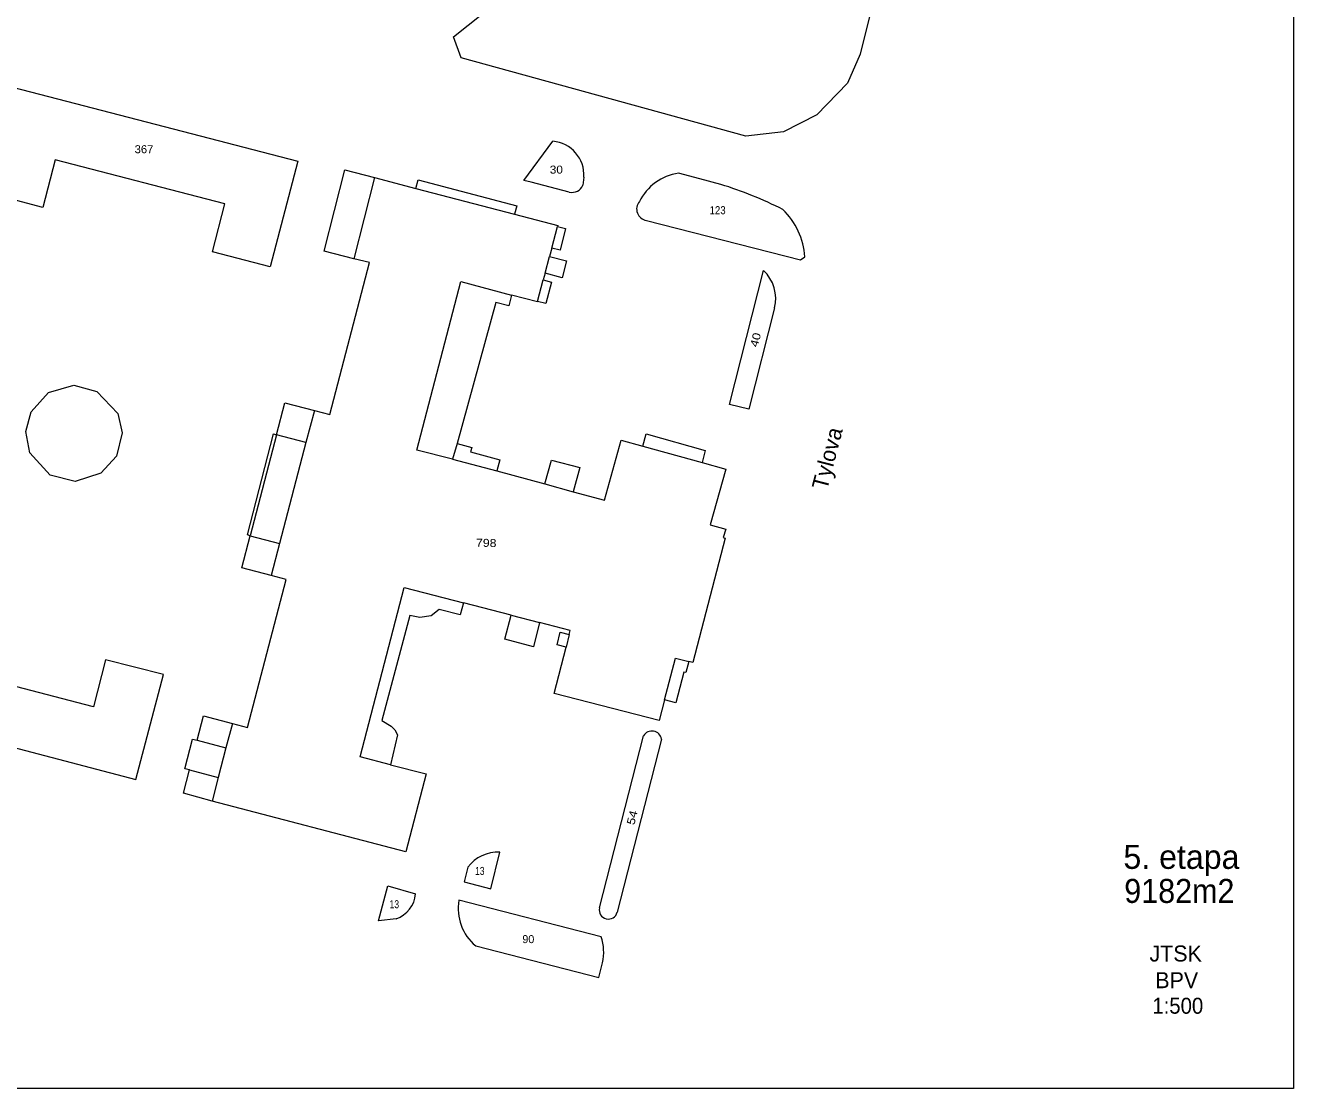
# Model space of a CAD drawing. Extents: x -843398 to -843100, y -1003450 to -1003185.
# Drawn here: x -843258.5 to -843100, y -1003450.4 to -1003317.5 of the extents above; entities that cross this region are included whole.
import ezdxf
from ezdxf.enums import TextEntityAlignment as Align

# ---------------------------------------------------------------- set-up
doc = ezdxf.new("R2010")
doc.units = 0
doc.header["$LTSCALE"] = 0.4
doc.layers.add('20', color=7, linetype='Continuous')
for name, color, linetype, lineweight in [('35', 7, 'Continuous', 13), ('36', 7, 'Continuous', 13), ('38', 7, 'Continuous', 13), ('43', 7, 'Continuous', 13), ('44', 7, 'Continuous', 13)]:
    doc.layers.add(name, color=color, linetype=linetype, lineweight=lineweight)

msp = doc.modelspace()

# ---------------------------------------------------------------- linework, layer by layer
at = {"layer": '36'}
for p, q in [((-843214.84, -1003336.5), (-843217.4, -1003346.66)), ((-843209.67, -1003337.87), (-843197.32, -1003341.09)), ((-843192.67, -1003345.33), (-843191.95, -1003342.62)), ((-843193.52, -1003348.48), (-843192.95, -1003346.37)), ((-843194.46, -1003352.01), (-843193.74, -1003349.31)), ((-843181.28, -1003370.1), (-843173.9, -1003372.15)), ((-843193.54, -1003374.82), (-843190.01, -1003375.79)), ((-843197.76, -1003391.23), (-843194.21, -1003392.15)), ((-843190.49, -1003393.65), (-843190.9, -1003395.24)), ((-843237, -1003406.86), (-843233.4, -1003407.8)), ((-843237.97, -1003410.57), (-843234.37, -1003411.51))]:
    msp.add_line(p, q, dxfattribs=at)
for points in [[(-843205.07, -1003371.72), (-843209.54, -1003370.58), (-843204.05, -1003349.5), (-843197.7, -1003351.2)], [(-843222.35, -1003365.62), (-843223.4, -1003369.63), (-843226.69, -1003382.25), (-843227.74, -1003386.26)], [(-843223.4, -1003369.63), (-843227.08, -1003368.67), (-843230.37, -1003381.29), (-843226.69, -1003382.25)], [(-843204.52, -1003369.77), (-843205.07, -1003371.72), (-843199.55, -1003373.19)], [(-843212.84, -1003409.91), (-843216.64, -1003408.92), (-843211.12, -1003387.76), (-843203.72, -1003389.68)], [(-843178.57, -1003401.8), (-843177.21, -1003396.58), (-843175.55, -1003397.01)], [(-843232.6, -1003404.75), (-843233.4, -1003407.8), (-843234.37, -1003411.51), (-843235.14, -1003414.48)]]:
    msp.add_lwpolyline(points, dxfattribs=at)
msp.add_lwpolyline([(-843255.58, -1003363.39), (-843252.41, -1003362.48), (-843249.54, -1003363.25), (-843246.92, -1003366.03), (-843246.39, -1003368.44), (-843247.1, -1003371.33), (-843249.04, -1003373.47), (-843252.23, -1003374.5), (-843255.39, -1003373.7), (-843257.9, -1003370.92), (-843258.41, -1003368.27), (-843257.77, -1003365.8)], close=True, dxfattribs=at)
at = {"layer": '38'}
msp.add_lwpolyline([(-843210.9, -1003420.8), (-843235.14, -1003414.48), (-843238.72, -1003413.46), (-843237.97, -1003410.57), (-843238.56, -1003410.41), (-843237.6, -1003406.71), (-843237, -1003406.86), (-843236.21, -1003403.82), (-843232.6, -1003404.75), (-843230.7, -1003405.25), (-843225.87, -1003386.75), (-843227.74, -1003386.26), (-843231.42, -1003385.3), (-843230.37, -1003381.29), (-843230.73, -1003381.19), (-843227.44, -1003368.57), (-843227.08, -1003368.67), (-843226.03, -1003364.66), (-843222.35, -1003365.62), (-843220.43, -1003366.12), (-843215.48, -1003347.15), (-843217.4, -1003346.66), (-843221.11, -1003345.73), (-843218.54, -1003335.56), (-843214.84, -1003336.5), (-843209.67, -1003337.87), (-843209.39, -1003336.81), (-843197.04, -1003340.03), (-843197.32, -1003341.09), (-843191.92, -1003342.5), (-843191.95, -1003342.62), (-843190.96, -1003342.88), (-843191.63, -1003345.6), (-843192.67, -1003345.33), (-843192.95, -1003346.37), (-843190.84, -1003346.93), (-843191.4, -1003349.05), (-843193.52, -1003348.48), (-843193.74, -1003349.31), (-843192.72, -1003349.58), (-843193.44, -1003352.28), (-843194.46, -1003352.01), (-843194.47, -1003352.06), (-843197.7, -1003351.2), (-843198.06, -1003352.56), (-843199.69, -1003352.13), (-843204.52, -1003369.77), (-843202.68, -1003370.27), (-843202.83, -1003370.82), (-843199.17, -1003371.81), (-843199.55, -1003373.19), (-843193.54, -1003374.82), (-843192.73, -1003371.83), (-843189.19, -1003372.78), (-843190.01, -1003375.79), (-843186.09, -1003376.86), (-843184, -1003369.34), (-843181.28, -1003370.1), (-843180.88, -1003368.57), (-843173.5, -1003370.62), (-843173.9, -1003372.15), (-843170.94, -1003372.97), (-843172.87, -1003379.92), (-843170.94, -1003380.45), (-843171.24, -1003381.52), (-843171.02, -1003381.58), (-843175.06, -1003397.14), (-843175.55, -1003397.01), (-843175.91, -1003398.4), (-843176.19, -1003398.33), (-843177.19, -1003402.16), (-843178.57, -1003401.8), (-843179.24, -1003404.37), (-843192.38, -1003401.01), (-843190.9, -1003395.24), (-843192.02, -1003394.95), (-843191.61, -1003393.36), (-843190.49, -1003393.65), (-843190.36, -1003393.15), (-843194.21, -1003392.15), (-843194.98, -1003395.16), (-843198.54, -1003394.24), (-843197.76, -1003391.23), (-843203.72, -1003389.68), (-843204.11, -1003391.2), (-843206.76, -1003390.52), (-843207.74, -1003391.3), (-843209.19, -1003391.53), (-843210.41, -1003391.25), (-843213.9, -1003404.4), (-843212.75, -1003405.09), (-843212.31, -1003405.54), (-843211.95, -1003406.2), (-843212.84, -1003409.91), (-843208.36, -1003411.07)], close=True, dxfattribs=at)
at = {"layer": '43'}
for p, q in [((-843196.167, -1003336.865), (-843192.547, -1003331.975)), ((-843188.662, -1003336.457), (-843188.79, -1003337.472)), ((-843170.474, -1003364.866), (-843166.22, -1003348.14)), ((-843186.719, -1003427.811), (-843181.2, -1003406.299)), ((-843178.973, -1003406.708), (-843184.5, -1003428.34)), ((-843200.306, -1003425.42), (-843199.173, -1003420.858)), ((-843213.185, -1003425.059), (-843209.697, -1003426.049)), ((-843186.486, -1003431.422), (-843204.283, -1003426.86))]:
    msp.add_line(p, q, dxfattribs=at)
for points in [[(-843204.95, -1003318.93), (-843183.6, -1003301.89), (-843179.12, -1003299.8), (-843172.43, -1003298.33), (-843165.55, -1003297.79), (-843149.07, -1003300.75), (-843154.15, -1003321.09), (-843155.7, -1003324.72), (-843159.53, -1003328.69), (-843163.73, -1003330.78), (-843168.41, -1003331.35), (-843204.02, -1003321.54)], [(-843263.55, -1003338.36), (-843260.1, -1003325.2), (-843224.42, -1003334.47), (-843227.87, -1003347.69), (-843235.07, -1003345.8), (-843233.55, -1003339.82), (-843254.77, -1003334.29), (-843256.29, -1003340.24)], [(-843244.66, -1003411.78), (-843241.23, -1003398.65), (-843248.44, -1003396.82), (-843249.97, -1003402.67), (-843271.24, -1003397.13), (-843269.61, -1003391.19), (-843276.83, -1003389.31), (-843280.36, -1003402.39)]]:
    msp.add_lwpolyline(points, close=True, dxfattribs=at)
for points in [[(-843171.55, -1003337.37), (-843174.19, -1003336.66), (-843176.842, -1003335.983)], [(-843190.487, -1003338.329), (-843195.26, -1003337.099), (-843196.167, -1003336.865)], [(-843180.84, -1003341.87), (-843161.595, -1003346.782), (-843161.047, -1003346.437)], [(-843164.84, -1003352.82), (-843168.06, -1003365.48), (-843170.474, -1003364.866)], [(-843203.174, -1003422.734), (-843203.647, -1003424.547), (-843200.306, -1003425.42)], [(-843212.142, -1003429.172), (-843214.337, -1003429.444), (-843213.185, -1003425.059)], [(-843202.187, -1003432.559), (-843186.811, -1003436.5), (-843186.342, -1003434.669)]]:
    msp.add_lwpolyline(points, dxfattribs=at)
for centre, radius, start, end in [((-843192.901, -1003336.206), 4.2462, 356.61099, 85.21833), ((-843175.9025, -1003342.4335), 6.5184, 98.28546, 153.44375), ((-843190.1358, -1003336.9153), 1.4562, 256.06082, 337.53429), ((-843187.6938, -1003388.5787), 53.6931, 63.56431, 72.50227), ((-843180.6309, -1003340.4456), 1.4399, 139.96096, 261.64539), ((-843170.2936, -1003347.1075), 9.2712, 4.14852, 45.4542), ((-843169.4711, -1003351.6421), 4.7785, 345.72972, 47.12888), ((-843180.1616, -1003406.9133), 1.2065, 9.78842, 149.37836), ((-843199.3985, -1003425.5827), 4.7298, 87.26743, 142.96216), ((-843213.2526, -1003425.7843), 3.5653, 288.14724, 355.73678), ((-843198.3523, -1003427.9141), 6.0232, 169.92007, 230.45301), ((-843185.6079, -1003428.0681), 1.1408, 166.97421, 346.21187), ((-843192.2663, -1003433.3055), 6.0796, 347.03881, 18.05061)]:
    msp.add_arc(centre, radius, start, end, dxfattribs=at)
at = {"layer": '44'}
msp.add_lwpolyline([(-843397.952, -1003184.571), (-843099.952, -1003184.571), (-843099.952, -1003394.571), (-843099.952, -1003450.409), (-843397.952, -1003450.409)], close=True, dxfattribs=at)

# ---------------------------------------------------------------- texts
at = {"layer": '20'}
msp.add_text('Tylova', height=1.999, rotation=75.482, dxfattribs=at).set_placement((-843158.263, -1003375.668))
at = {"layer": '35', "width": 1.15}
msp.add_text('798', height=1, rotation=358.734, dxfattribs=at).set_placement((-843200.8815, -1003382.681), align=Align.CENTER)
at = {"layer": '43'}
for s, width, p in [('367', 1.05, (-843244.82, -1003333.475)), ('30', 1.1, (-843192.926, -1003336.021)), ('123', 0.9, (-843172.952, -1003341.096)), ('13', 0.8, (-843202.271, -1003423.691)), ('13', 0.8, (-843212.952, -1003427.855))]:
    msp.add_text(s, height=1, dxfattribs=dict(at, width=width)).set_placement(p)
at = {"layer": '43', "width": 1.2}
for s, height, rotation, p in [('40', 1, 75.73, (-843166.948, -1003357.789)), ('54', 0.999, 75.633, (-843182.371, -1003417.516))]:
    msp.add_text(s, height=height, rotation=rotation, dxfattribs=at).set_placement(p)
at = {"layer": '43'}
msp.add_text('90', height=1, dxfattribs=at).set_placement((-843196.352, -1003432.217))
at = {"layer": '44'}
for s, height, p in [('5. etapa', 3, (-843121.227, -1003422.937)), ('JTSK', 2, (-843117.965, -1003434.516)), ('BPV', 2, (-843117.236, -1003437.851))]:
    msp.add_text(s, height=height, dxfattribs=at).set_placement(p)
at = {"layer": '44', "width": 0.95}
for s, height, p in [('9182m2', 3, (-843121.122, -1003427.193)), ('1:500', 2, (-843117.611, -1003441.045))]:
    msp.add_text(s, height=height, dxfattribs=at).set_placement(p)

doc.saveas('drawing.dxf')
